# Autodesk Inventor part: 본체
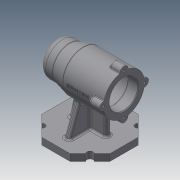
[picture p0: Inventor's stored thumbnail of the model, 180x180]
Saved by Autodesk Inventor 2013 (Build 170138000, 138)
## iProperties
Created: 2021-01
Part Number: 본체
Material: Generic
Document SubType Name: Modeling
Designer: 19
Density: 1 g/cm^3
Author: 19
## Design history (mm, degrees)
sketch "스케치1"
  geometry: L1 (-50, 0)-(50, 0); L2 (-50, 0)-(-50, 15); L3 (-40, 25)-(-30, 25); L4 (-30, 25)-(-10, 30); L5 (-10, 30)-(50, 30); L6 (50, 30)-(50, 22); L7 (49, 21)-(35, 21); L8 (35, 21)-(35, 21); L9 (32, 24)-(-4, 24); L10 (-7, 21)-(-7, 21); L11 (-7, 21)-(-18.7, 21); L12 (-19, 20.7)-(-19, 17.5); L13 (-19, 17.5)-(-36.7, 17.5); L14 (-37, 17.2)-(-37, 16); L15 (-37, 16)-(-40.7, 16); L16 (-41, 15.7)-(-41, 10.5); L17 (-41, 10.5)-(-41, 10.5); L18 (-44, 7.5)-(-44, 0); L19 (49, 21)-(50, 22); A1 r 3 centre (-41, 7.5) between (-41, 10.5) and (-44, 7.5); A2 r 3 centre (-4, 21) between (-4, 24) and (-7, 21); A3 r 3 centre (32, 21) between (35, 21) and (32, 24); A4 r 0.3 centre (-40.7, 15.7) between (-40.7, 16) and (-41, 15.7); A5 r 0.3 centre (-36.7, 17.2) between (-36.7, 17.5) and (-37, 17.2); A6 r 0.3 centre (-18.7, 20.7) between (-18.7, 21) and (-19, 20.7); A7 r 10 centre (-40, 15) between (-40, 25) and (-50, 15); 11 further points
  constraints: 38 end point, 20 point on line, 14 point on circle, 14 tangent, 9 parallel, 7 centre point, 6 perpendicular, 4 equal radius, 1 coincident, 1 collinear, 1 horizontal, 1 midpoint
  dimensions: "d0" = 100 distance of L1.start L1.end; "d1" = 60 diameter of L5 L1; "d2" = 50 diameter of L3 L1; "d3" = 20 distance of point (-50, 25) L3.end; "d4" = 40 distance from line of L2 L4.end; "d5" = 42 diameter of L7 L1; "d6" = 48 diameter of L9 L1; "d7" = 42 diameter of L11 L1 (= d5); "d8" = 35 diameter of L13 L1; "d9" = 32 diameter of L15 L1; "d10" = 21 diameter of L17 L1; "d11" = 15 distance of point (50, 21) L7.end; "d12" = 42 distance of point (35, 24) point (-7, 24); "d13" = 12 distance of L10.end point (-19, 21); "d14" = 18 distance of L12.end point (-37, 17.5); "d15" = 4 distance of L14.end point (-41, 16); "d16" = 3 distance of L16.end point (-44, 10.5); "d17" = 3 radius of A1; "d18" = 0.3 radius of A4; "d19" = 1 distance of L7.start point (50, 21); "d20" = 1 distance of L6.end point (50, 21) (= d19); "d21" = 10 radius of A7
revolve "회전1" sketch "스케치1" stored, may be unused: angle "d22" = 90 deg
node "작업 평면1"
sketch "스케치2"
  geometry: L1 (-50, 20.711)-(-20.711, 50); L2 (-20.711, 50)-(20.711, 50); L3 (20.711, 50)-(50, 20.711); L4 (50, 20.711)-(50, -20.711); L5 (50, -20.711)-(20.711, -50); L6 (20.711, -50)-(-20.711, -50); L7 (-20.711, -50)-(-50, -20.711); L8 (-50, -20.711)-(-50, 20.711); L9 (-50, 30)-(-50, -30) reference; L10 (-35.355, -35.355)-(35.355, 35.355); L11 (-35.355, 35.355)-(35.355, -35.355); A1 r 50 centre (0, 0) between (-35.355, 35.355) and (-35.355, -35.355); A2 r 4.5 centre (35.355, -35.355) between (38.537, -32.173) and (32.173, -38.537); A3 r 4.5 centre (-35.355, 35.355) between (-38.537, 32.173) and (-32.173, 38.537); A4 r 4.5 centre (35.355, 35.355) between (32.173, 38.537) and (38.537, 32.173); A5 r 4.5 centre (-35.355, -35.355) between (-32.173, -38.537) and (-38.537, -32.173); A6 r 4.5 centre (35.355, -35.355) between (32.173, -38.537) and (38.537, -32.173); A7 r 4.5 centre (-35.355, -35.355) between (-38.537, -32.173) and (-32.173, -38.537); A8 r 4.5 centre (-35.355, 35.355) between (-32.173, 38.537) and (-38.537, 32.173); A9 r 4.5 centre (35.355, 35.355) between (38.537, 32.173) and (32.173, 38.537); 2 further points
  constraints: 20 end point, 19 point on circle, 9 centre point, 8 point on line, 5 midpoint, 2 coincident, 1 collinear, 17 other
  dimensions: "d24" = 100 diameter of A1; "d25" = 50 distance from line of point (0, 0) L6; "d26" = 9 diameter of A2; "d27" = 9 diameter of A3; "d28" = 9 diameter of A4; "d29" = 9 diameter of A5
extrude "돌출1" join sketch "스케치2" distance "d30" = 10; taper "d31" = 0 deg
sketch "스케치5"
  geometry: L1 (50, -20.711)-(50, 20.711) reference; L2 (-50, 20.711)-(-50, -20.711) reference; L3 (-27, -4)-(27, -4); L4 (27, -4)-(27, 4); L5 (27, 4)-(-27, 4); L6 (-27, 4)-(-27, -4); 1 further point
  constraints: 8 end point, 2 parallel, 1 horizontal, 1 perpendicular
  dimensions: "d37" = 8 distance of L3.end L4.end; "d39" = 23 distance between parallel lines of L1 L4; "d40" = 23 distance between parallel lines of L2 L6; "d41" = 4 distance from line of L5 point (0, 0)
extrude "돌출3" join sketch "스케치5" stored distance "d42" = 8; taper "d43" = 0 deg
feature "면 기울기1" dims angle "d44" = 11 deg
sketch "스케치6"
  geometry: L1 (-65, -50)-(-75, -50) reference; L2 (-75, -50)-(-75, 50) reference; L3 (-75, 50)-(-65, 50) reference; L4 (-65, 50)-(-65, 4) reference; L5 (-65, 4)-(-29.732, 4) reference; L6 (-29.732, -4)-(-65, -4) reference; L7 (-65, -4)-(-65, -50) reference; L8 (-65, 35)-(-22.707, 19.606); L9 (-22.707, -19.606)-(-65, -35); C1 r 24 at (0, 0) reference; A1 r 30 centre (0, 0) between (-29.732, -4) and (-29.732, 4) reference; 1 further point
  constraints: 4 end point, 2 point on circle, 2 point on line
  dimensions: "d45" = 15 distance from line of L9.end L1; "d46" = 15 distance from line of L3 L8.start; "d47" = 110 deg angle of L7 L9; "d48" = 110 deg angle of L4 L8
extrude "돌출4" join sketch "스케치6" stored distance "d49" = 8; taper "d50" = 0 deg
sketch "스케치7"
  geometry: C1 r 22 at (0, 0) reference; C2 r 6 at (0, 30); 1 further point
  constraints: 2 vertical alignment, 1 centre point, 1 other
  dimensions: "d51" = 12 diameter of C2
extrude "돌출5" join sketch "스케치7" distance "d52" = 16; taper "d53" = 0 deg
sketch "스케치8"
  geometry: A1 r 6 centre (0, 0) between (5.97, -0.6) and (-5.97, -0.6) reference; 1 further point
  constraints: 1 coincident
hole "구멍1" sketch "스케치8" at (0, 0) diameter "d54" = 3.242; stored, may be unused: countersink angle "d58" = 90 deg, drill point angle "d60" = 118 deg; dims "d55" = 8, "d56" = 4, "d57" = 2, "d59" = 10
fillet "모깎기1" dims "d61" = 3
fillet "모깎기2" dims "d65" = 3
fillet "모깎기3" dims "d66" = 3
fillet "모깎기4" dims "d67" = 1
fillet "모깎기5" dims "d68" = 3
node "작업 평면2"
sketch "스케치9"
  geometry: L1 (50, 6.771)-(50, 29.226) reference; 2 further points
  constraints: 1 horizontal alignment, 1 other
  dimensions: "d70" = 38 distance from line of point (12, 0) L1
feature "엠보싱1" sketch "스케치9" dims "d71" = 0.5, "d72" = 0
node "솔리드1"
pattern_circular "원형 패턴1" dims "d63" = 360 deg
node "절단 모서리 투영3"
other parameters: "d23" = -75, "d69" = 71
